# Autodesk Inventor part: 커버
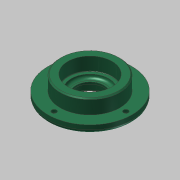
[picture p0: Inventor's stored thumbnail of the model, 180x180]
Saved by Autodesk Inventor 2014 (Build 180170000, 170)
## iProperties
Company: 한국ATC센터
Created: 2016-04
Part Number: 커버
Document SubType Name: Modeling
Designer: mdu
Density: 7.86 g/cm^3
Mass: 324.808 g
Surface Area: 150.575 cm^2
Volume: 41.3241 cm^3
Material: 강철, 연강
Appearance: 강철
Author: mdu
Revision Number: 1
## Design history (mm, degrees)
sketch "스케치1"
  geometry: C1 r 38 at (0, 0); 1 further point
  constraints: 1 centre point, 1 coincident
  dimensions: "d0" = 76 diameter of C1
extrude "돌출1" new body sketch "스케치1" distance "d1" = 7; taper "d2" = 0 deg
sketch "스케치2"
  geometry: C1 r 27 at (0, 0); 1 further point
  constraints: 1 centre point, 1 coincident
  dimensions: "d3" = 54 diameter of C1
extrude "돌출2" join sketch "스케치2" distance "d4" = 13; taper "d5" = 0 deg
sketch "스케치3"
  geometry: C1 r 20 at (0, 0); 1 further point
  constraints: 1 centre point, 1 coincident
  dimensions: "d6" = 40 diameter of C1
extrude "돌출3" join sketch "스케치3" distance "d7" = 5; taper "d8" = 0 deg
hole "구멍1" diameter "d11" = 25; stored, may be unused: countersink angle "d15" = 90 deg, drill point angle "d17" = 118 deg; dims "d9" = 10, "d10" = 10, "d12" = 6, "d13" = 32, "d14" = 8.3, "d16" = 8
hole "구멍2" diameter "d20" = 34; stored, may be unused: countersink angle "d24" = 90 deg, drill point angle "d26" = 0 deg; dims "d18" = 10, "d19" = 10, "d21" = 6, "d22" = 40, "d23" = 12, "d25" = 3
fillet "모깎기2" dims "d34" = 3
fillet "모깎기1" dims "d27" = 0.3
chamfer "모따기1" distance "d28" = 1; stored, may be unused: second distance "d29" = 2, angle "d30" = 45 deg
chamfer "모따기2" distance "d31" = 1.2; stored, may be unused: second distance "d32" = 2, angle "d33" = 30 deg
sketch "스케치4" dims "d35" = 65
  geometry: 3 further points
  constraints: 2 horizontal alignment, 1 coincident, 2 other
hole "구멍3" sketch "스케치4" at (32.5, 0) diameter "d36" = 4.5; stored, may be unused: countersink angle "d40" = 90 deg, drill point angle "d42" = 118 deg; dims "d37" = 6, "d38" = 8, "d39" = 4.4, "d41" = 13
node "솔리드1"
pattern_circular "원형 패턴1" dims angle "d44" = 360 deg
